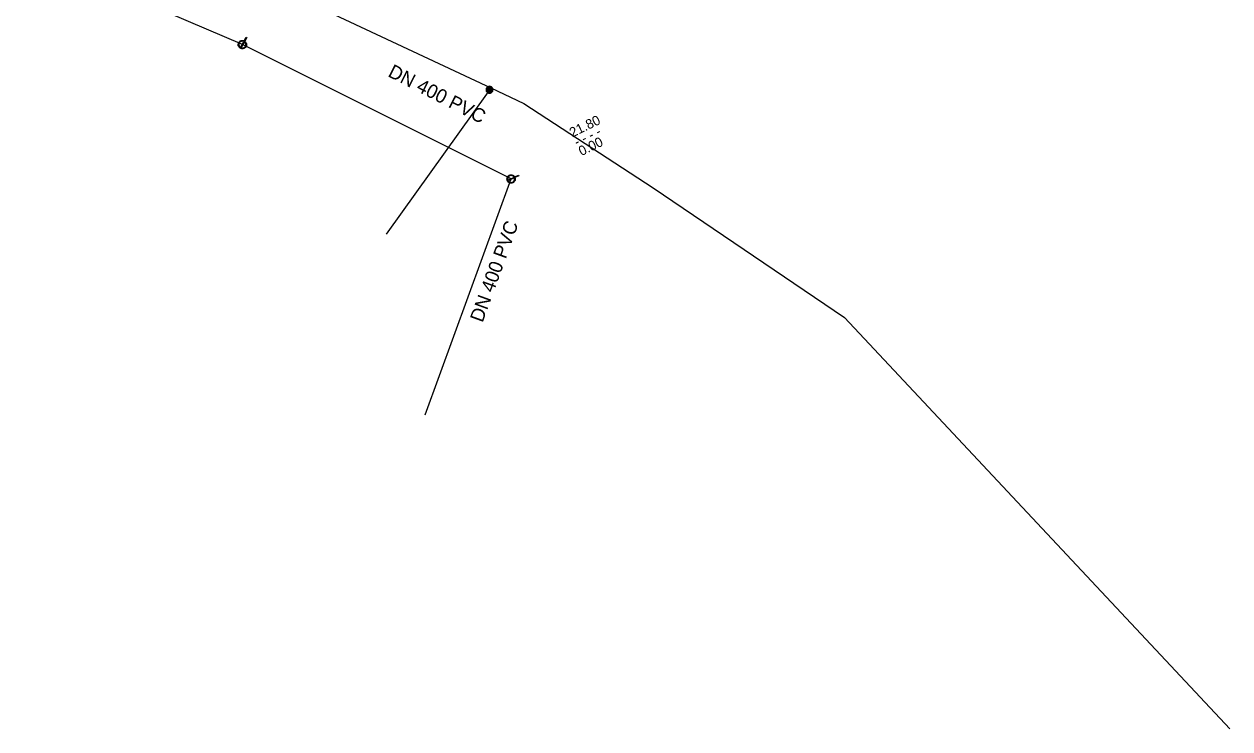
# Model space of a CAD drawing. Extents: x -818321 to -817653, y -1049725 to -1049329.
# Drawn here: x -818061.8 to -817974.4, y -1049508.9 to -1049457.8 of the extents above; entities that cross this region are included whole.
import ezdxf

# ---------------------------------------------------------------- set-up
doc = ezdxf.new("R2010")
doc.units = 0
doc.layers.add('Default', color=7, linetype='Continuous')
doc.layers.add('Level 0', color=7, linetype='Continuous')

msp = doc.modelspace()

# ---------------------------------------------------------------- linework, layer by layer
at = {"layer": 'Default'}
for points in [[(-818046.076, -1049459.505), (-818045.827, -1049459.074)], [(-818045.784, -1049459.099), (-818046.033, -1049459.53)], [(-818045.802, -1049459.03), (-818045.651, -1049458.77), (-818045.609, -1049458.794), (-818045.759, -1049459.055)], [(-818026.687, -1049469.132), (-818026.24, -1049468.914)], [(-818026.219, -1049468.958), (-818026.666, -1049469.176)], [(-818026.194, -1049468.891), (-818025.924, -1049468.76), (-818025.903, -1049468.804), (-818026.173, -1049468.936)]]:
    msp.add_lwpolyline(points, dxfattribs=at)
for points in [[(-818045.759, -1049459.055), (-818045.707, -1049459.089), (-818045.67, -1049459.151), (-818045.628, -1049459.221), (-818045.63, -1049459.303), (-818045.631, -1049459.384), (-818045.67, -1049459.452), (-818045.709, -1049459.52), (-818045.78, -1049459.562), (-818045.852, -1049459.604), (-818045.933, -1049459.602), (-818046.014, -1049459.6), (-818046.08, -1049459.562), (-818046.145, -1049459.524), (-818046.188, -1049459.454), (-818046.231, -1049459.385), (-818046.23, -1049459.302), (-818046.229, -1049459.22), (-818046.19, -1049459.152), (-818046.151, -1049459.084), (-818046.081, -1049459.042), (-818046.011, -1049459), (-818045.929, -1049459.002), (-818045.857, -1049459.003), (-818045.802, -1049459.03)], [(-818045.827, -1049459.074), (-818045.871, -1049459.053), (-818045.93, -1049459.052), (-818045.998, -1049459.051), (-818046.056, -1049459.086), (-818046.114, -1049459.12), (-818046.147, -1049459.177), (-818046.179, -1049459.233), (-818046.18, -1049459.302), (-818046.181, -1049459.371), (-818046.145, -1049459.429), (-818046.115, -1049459.478), (-818046.076, -1049459.505)], [(-818046.033, -1049459.53), (-818045.99, -1049459.55), (-818045.932, -1049459.552), (-818045.864, -1049459.554), (-818045.805, -1049459.519), (-818045.746, -1049459.483), (-818045.713, -1049459.427), (-818045.681, -1049459.371), (-818045.68, -1049459.303), (-818045.678, -1049459.235), (-818045.714, -1049459.177), (-818045.744, -1049459.127), (-818045.784, -1049459.099)], [(-818028.019, -1049462.327), (-818027.956, -1049462.327), (-818027.896, -1049462.359), (-818027.836, -1049462.392), (-818027.802, -1049462.452), (-818027.769, -1049462.512), (-818027.769, -1049462.577), (-818027.769, -1049462.642), (-818027.802, -1049462.702), (-818027.835, -1049462.761), (-818027.894, -1049462.794), (-818027.954, -1049462.827), (-818028.019, -1049462.827), (-818028.084, -1049462.827), (-818028.143, -1049462.794), (-818028.203, -1049462.761), (-818028.236, -1049462.702), (-818028.269, -1049462.642), (-818028.269, -1049462.577), (-818028.269, -1049462.512), (-818028.235, -1049462.452), (-818028.201, -1049462.392), (-818028.142, -1049462.359), (-818028.082, -1049462.327), (-818028.019, -1049462.327)], [(-818028.019, -1049462.351), (-818028.076, -1049462.351), (-818028.13, -1049462.38), (-818028.184, -1049462.409), (-818028.215, -1049462.464), (-818028.245, -1049462.518), (-818028.245, -1049462.577), (-818028.245, -1049462.636), (-818028.215, -1049462.69), (-818028.186, -1049462.744), (-818028.132, -1049462.774), (-818028.077, -1049462.804), (-818028.019, -1049462.804), (-818027.96, -1049462.804), (-818027.906, -1049462.774), (-818027.852, -1049462.744), (-818027.822, -1049462.69), (-818027.792, -1049462.636), (-818027.792, -1049462.577), (-818027.792, -1049462.518), (-818027.823, -1049462.464), (-818027.854, -1049462.409), (-818027.908, -1049462.38), (-818027.962, -1049462.351), (-818028.019, -1049462.351)], [(-818028.019, -1049462.368), (-818027.966, -1049462.368), (-818027.916, -1049462.395), (-818027.866, -1049462.422), (-818027.838, -1049462.472), (-818027.809, -1049462.523), (-818027.809, -1049462.577), (-818027.809, -1049462.632), (-818027.837, -1049462.682), (-818027.864, -1049462.731), (-818027.914, -1049462.759), (-818027.964, -1049462.787), (-818028.019, -1049462.787), (-818028.073, -1049462.787), (-818028.123, -1049462.759), (-818028.173, -1049462.731), (-818028.201, -1049462.682), (-818028.228, -1049462.632), (-818028.228, -1049462.577), (-818028.228, -1049462.523), (-818028.2, -1049462.472), (-818028.172, -1049462.422), (-818028.122, -1049462.395), (-818028.072, -1049462.368), (-818028.019, -1049462.368)], [(-818028.019, -1049462.39), (-818028.097, -1049462.39), (-818028.152, -1049462.445), (-818028.206, -1049462.5), (-818028.206, -1049462.577), (-818028.206, -1049462.655), (-818028.151, -1049462.71), (-818028.096, -1049462.765), (-818028.019, -1049462.765), (-818027.941, -1049462.765), (-818027.886, -1049462.71), (-818027.831, -1049462.655), (-818027.831, -1049462.577), (-818027.831, -1049462.5), (-818027.886, -1049462.445), (-818027.94, -1049462.39), (-818028.019, -1049462.39)], [(-818028.019, -1049462.413), (-818027.95, -1049462.413), (-818027.903, -1049462.461), (-818027.855, -1049462.509), (-818027.855, -1049462.577), (-818027.855, -1049462.645), (-818027.903, -1049462.693), (-818027.951, -1049462.741), (-818028.019, -1049462.741), (-818028.087, -1049462.741), (-818028.135, -1049462.693), (-818028.183, -1049462.645), (-818028.183, -1049462.577), (-818028.183, -1049462.509), (-818028.135, -1049462.461), (-818028.087, -1049462.413), (-818028.019, -1049462.413)], [(-818028.019, -1049462.432), (-818028.079, -1049462.432), (-818028.121, -1049462.475), (-818028.163, -1049462.517), (-818028.163, -1049462.577), (-818028.163, -1049462.637), (-818028.121, -1049462.679), (-818028.079, -1049462.721), (-818028.019, -1049462.721), (-818027.959, -1049462.721), (-818027.917, -1049462.679), (-818027.875, -1049462.637), (-818027.875, -1049462.577), (-818027.875, -1049462.517), (-818027.917, -1049462.475), (-818027.959, -1049462.432), (-818028.019, -1049462.432)], [(-818028.019, -1049462.452), (-818027.966, -1049462.452), (-818027.93, -1049462.489), (-818027.894, -1049462.525), (-818027.894, -1049462.577), (-818027.894, -1049462.629), (-818027.93, -1049462.666), (-818027.967, -1049462.702), (-818028.019, -1049462.702), (-818028.07, -1049462.702), (-818028.107, -1049462.666), (-818028.144, -1049462.629), (-818028.144, -1049462.577), (-818028.144, -1049462.525), (-818028.107, -1049462.489), (-818028.071, -1049462.452), (-818028.019, -1049462.452)], [(-818028.019, -1049462.475), (-818028.061, -1049462.475), (-818028.091, -1049462.505), (-818028.12, -1049462.535), (-818028.12, -1049462.577), (-818028.12, -1049462.619), (-818028.091, -1049462.649), (-818028.061, -1049462.679), (-818028.019, -1049462.679), (-818027.977, -1049462.679), (-818027.947, -1049462.649), (-818027.917, -1049462.619), (-818027.917, -1049462.577), (-818027.917, -1049462.535), (-818027.947, -1049462.505), (-818027.977, -1049462.475), (-818028.019, -1049462.475)], [(-818028.019, -1049462.493), (-818027.984, -1049462.493), (-818027.959, -1049462.517), (-818027.935, -1049462.542), (-818027.935, -1049462.577), (-818027.935, -1049462.612), (-818027.959, -1049462.637), (-818027.984, -1049462.661), (-818028.019, -1049462.661), (-818028.054, -1049462.661), (-818028.079, -1049462.637), (-818028.103, -1049462.612), (-818028.103, -1049462.577), (-818028.103, -1049462.542), (-818028.079, -1049462.517), (-818028.054, -1049462.493), (-818028.019, -1049462.493)], [(-818028.019, -1049462.515), (-818028.045, -1049462.515), (-818028.063, -1049462.533), (-818028.081, -1049462.551), (-818028.081, -1049462.577), (-818028.081, -1049462.603), (-818028.063, -1049462.621), (-818028.044, -1049462.64), (-818028.019, -1049462.64), (-818027.993, -1049462.64), (-818027.974, -1049462.621), (-818027.956, -1049462.603), (-818027.956, -1049462.577), (-818027.956, -1049462.551), (-818027.974, -1049462.533), (-818027.992, -1049462.515), (-818028.019, -1049462.515)], [(-818028.019, -1049462.538), (-818028.002, -1049462.538), (-818027.991, -1049462.549), (-818027.98, -1049462.561), (-818027.98, -1049462.577), (-818027.98, -1049462.593), (-818027.991, -1049462.605), (-818028.002, -1049462.616), (-818028.019, -1049462.616), (-818028.035, -1049462.616), (-818028.046, -1049462.605), (-818028.058, -1049462.593), (-818028.058, -1049462.577), (-818028.058, -1049462.561), (-818028.046, -1049462.549), (-818028.035, -1049462.538), (-818028.019, -1049462.538)], [(-818028.019, -1049462.554), (-818028.029, -1049462.554), (-818028.035, -1049462.56), (-818028.042, -1049462.567), (-818028.042, -1049462.577), (-818028.042, -1049462.587), (-818028.035, -1049462.594), (-818028.029, -1049462.601), (-818028.019, -1049462.601), (-818028.009, -1049462.601), (-818028.002, -1049462.594), (-818027.995, -1049462.587), (-818027.995, -1049462.577), (-818027.995, -1049462.567), (-818028.002, -1049462.56), (-818028.009, -1049462.554), (-818028.019, -1049462.554)], [(-818026.173, -1049468.936), (-818026.149, -1049468.993), (-818026.153, -1049469.065), (-818026.157, -1049469.147), (-818026.204, -1049469.213), (-818026.251, -1049469.28), (-818026.321, -1049469.314), (-818026.392, -1049469.349), (-818026.474, -1049469.344), (-818026.557, -1049469.339), (-818026.623, -1049469.292), (-818026.689, -1049469.245), (-818026.722, -1049469.176), (-818026.755, -1049469.108), (-818026.752, -1049469.027), (-818026.749, -1049468.945), (-818026.702, -1049468.878), (-818026.655, -1049468.81), (-818026.584, -1049468.775), (-818026.514, -1049468.741), (-818026.433, -1049468.745), (-818026.351, -1049468.749), (-818026.284, -1049468.796), (-818026.225, -1049468.837), (-818026.194, -1049468.891)], [(-818026.24, -1049468.914), (-818026.265, -1049468.871), (-818026.313, -1049468.837), (-818026.369, -1049468.799), (-818026.436, -1049468.795), (-818026.504, -1049468.791), (-818026.562, -1049468.82), (-818026.621, -1049468.848), (-818026.66, -1049468.905), (-818026.699, -1049468.962), (-818026.702, -1049469.03), (-818026.704, -1049469.087), (-818026.687, -1049469.132)], [(-818026.666, -1049469.176), (-818026.641, -1049469.217), (-818026.594, -1049469.251), (-818026.539, -1049469.291), (-818026.47, -1049469.295), (-818026.401, -1049469.298), (-818026.343, -1049469.27), (-818026.285, -1049469.241), (-818026.246, -1049469.186), (-818026.207, -1049469.13), (-818026.204, -1049469.062), (-818026.2, -1049469.004), (-818026.219, -1049468.958)]]:
    msp.add_open_spline(points, degree=3, dxfattribs=at)
at = {"layer": 'Level 0'}
for p, q in [((-818045.927, -1049459.297), (-818061.75, -1049452.52)), ((-818043.537, -1049455.115), (-818027.919, -1049462.438)), ((-818026.448, -1049469.043), (-818045.927, -1049459.297)), ((-818028.119, -1049462.716), (-818035.518, -1049473.042)), ((-818027.919, -1049462.438), (-818028.119, -1049462.716)), ((-818027.919, -1049462.438), (-818025.522, -1049463.561)), ((-818025.522, -1049463.561), (-818016.159, -1049469.679)), ((-818032.685, -1049486.146), (-818026.448, -1049469.043)), ((-818016.159, -1049469.679), (-818002.283, -1049479.074)), ((-818002.283, -1049479.074), (-817974.355, -1049508.895))]:
    msp.add_line(p, q, dxfattribs=at)

# ---------------------------------------------------------------- texts
for s, height, rotation, p in [('DN 400 PVC', 1, 333, (-818035.444, -1049461.578)), ('21.80', 0.7, 26, (-818022.011, -1049466.042)), ('- - - -', 0.7, 26, (-818021.681, -1049466.715)), ('0.00', 0.7, 26, (-818021.351, -1049467.389)), ('DN 400 PVC', 1, 70, (-818028.524, -1049479.497))]:
    msp.add_text(s, height=height, rotation=rotation, dxfattribs=at).set_placement(p)

doc.saveas('drawing.dxf')
